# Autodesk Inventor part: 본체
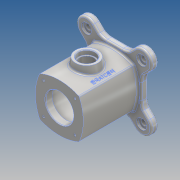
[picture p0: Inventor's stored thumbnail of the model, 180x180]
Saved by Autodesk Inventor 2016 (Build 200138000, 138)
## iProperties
Created: 2016-05
Part Number: 본체
Material: 알루미늄 6061
Document SubType Name: Modeling
Designer: Administrator
Density: 2.7 g/cm^3
Appearance: 알루미늄 - 평지
Mass: 1094 g
Surface Area: 856.534 cm^2
Volume: 405.187 cm^3
Author: Administrator
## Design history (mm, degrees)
sketch "스케치1"
  geometry: L1 (0, 0)-(-70.711, 70.711); L2 (0, 0)-(-118.695, 0); L3 (-70.711, 0)-(0, 70.711); L4 (7.604, 35.355)-(-78.314, 35.355); L5 (-35.355, -7.645)-(-35.355, 78.314); A1 r 86 centre (7.686, 35.355) between (-70.711, 70.711) and (-70.711, 0); A2 r 86 centre (-35.355, -7.686) between (0, 70.711) and (-70.711, 70.711); A3 r 85.162 centre (-77.476, 35.355) between (0, 0) and (0, 70.711); A4 r 85.162 centre (-35.355, 77.476) between (-70.711, 0) and (0, 0); 2 further points
  constraints: 12 point on circle, 10 end point, 4 centre point, 3 midpoint, 2 horizontal, 2 point on line, 1 perpendicular, 1 vertical
  dimensions: "d0" = 100 distance of L1.start L1.end; "d2" = 45 deg angle of L2 L1; "d3" = 100 distance of L3.start L3.end; "d4" = 50 distance from line of L1.start L3; "d103" = 86 distance of A1.centre L4.end; "d104" = 86 distance of A2.centre L5.end
extrude "돌출1" new body sketch "스케치1" distance "d9" = 98; taper "d10" = 0 deg
sketch "스케치4"
  geometry: L1 (35.355, -35.355)-(-104.696, -35.355); L2 (35.355, -35.355)-(35.355, -161.613); L3 (35.355, -35.355)-(-81.211, -151.922); L4 (-13.645, -35.355)-(-13.645, -61.423); L5 (35.355, -84.355)-(21.194, -84.355); L6 (-13.645, -49.517)-(-13.645, -35.355); L7 (-13.645, -35.355)-(35.355, -35.355); L8 (35.355, -35.355)-(35.355, -84.355); L9 (22.627, -22.627)-(-6.158, -51.413); L10 (-17.335, -62.59)-(-26.87, -72.125); L11 (8.121, -88.046)-(-1.414, -97.581); A1 r 85.162 centre (77.476, -35.355) between (0, 0) and (0, -70.711) reference; A2 r 85.162 centre (35.355, -77.476) between (70.711, 0) and (0, 0) reference; A3 r 70 centre (35.355, -35.355) between (-14.142, -84.853) and (0.117, -95.839); A4 r 18 centre (-14.142, -84.853) between (-26.87, -72.125) and (-1.414, -97.581); A5 r 25 centre (21.194, -109.355) between (21.194, -84.355) and (8.121, -88.046); A6 r 25 centre (-38.645, -49.517) between (-17.335, -62.59) and (-13.645, -49.517); 2 further points
  constraints: 22 end point, 11 point on circle, 4 centre point, 4 symmetric about line, 3 point on line, 2 collinear, 2 horizontal, 2 parallel, 2 tangent, 2 vertical, 1 horizontal alignment, 1 vertical alignment, 1 other
  dimensions: "d38" = 140 diameter of A3; "d39" = 45 deg angle of L2 L3; "d40" = 36 diameter of A4; "d42" = 49 distance between parallel lines of L4 L2; "d43" = 49 distance between parallel lines of L1 L5; "d44" = 50 diameter of A5; "d106" = 18 distance between parallel lines of L10 L3
extrude "돌출2" join sketch "스케치4" distance "d45" = 12; taper "d46" = 0 deg
node "작업 평면1"
node "작업 평면2"
node "작업 평면3"
node "작업 평면5"
  node "작업 평면4"
sketch "스케치6"
  geometry: L1 (49.517, -98)-(-21.194, -98) reference; L2 (-21.194, -98)-(49.517, -98) reference; L3 (49.517, -98)-(49.517, 0) reference; L4 (-21.194, 0)-(49.517, 0) reference; L5 (-21.194, -98)-(-21.194, 0) reference; L6 (-21.194, -98)-(-21.194, 0) reference; L7 (-21.194, -49)-(49.517, -49); L8 (49.517, -98)-(49.517, 0) reference; C1 r 20 at (14.162, -49)
  constraints: 3 midpoint, 2 end point, 1 centre point
  dimensions: "d50" = 40 diameter of C1
extrude "돌출3" join sketch "스케치6" distance "d51" = 50; taper "d52" = 10 deg
sketch "스케치7"
  geometry: L1 (21.194, -98)-(-49.517, -98) reference; L2 (-14.162, -98)-(-14.162, 12); L3 (0, 12)-(-28.323, 12) reference; L4 (10.838, -98)-(10.838, -86); L5 (10.838, -86)-(20.838, -86); L6 (20.838, -86)-(20.838, 0); L7 (20.838, 0)-(10.838, 0); L8 (10.838, 0)-(10.838, 12); L9 (0, 12)-(13.073, 12) reference; L10 (10.838, -98)-(-14.162, -98); L11 (10.272, 12)-(-14.162, 12); 1 further point
  constraints: 16 end point, 4 perpendicular, 3 point on line, 2 collinear, 2 midpoint, 1 vertical
  dimensions: "d53" = 70 diameter of L6 L2; "d54" = 86 distance between parallel lines of L7 L5; "d55" = 12 distance between parallel lines of L1 L5; "d56" = 50 diameter of L4 L2; "d57" = 50 diameter of L8 L2
revolve "회전1" sketch "스케치7" stored, may be unused: angle "d58" = 90 deg
sketch "스케치8"
  geometry: C1 r 20 at (0, 0) reference; 2 further points
  constraints: 1 coincident
hole "구멍1" sketch "스케치8" at (0, 0) diameter "d59" = 25; stored, may be unused: countersink angle "d63" = 90 deg, drill point angle "d65" = 0 deg; dims "d60" = 6, "d61" = 30, "d62" = 8, "d64" = 8
sketch "스케치10"
  geometry: A1 r 18 centre (84.853, -14.142) between (72.125, -26.87) and (97.581, -1.414) reference; A2 r 18 centre (84.853, 84.853) between (97.581, 72.125) and (72.125, 97.581) reference; A3 r 18 centre (-14.142, 84.853) between (-1.414, 97.581) and (-26.87, 72.125) reference; A4 r 18 centre (-14.142, -14.142) between (-26.87, -1.414) and (-1.414, -26.87) reference; 12 further points
  constraints: 4 coincident
hole "구멍2" sketch "스케치10" at (84.853, 84.853), (84.853, -14.142), (-14.142, -14.142), (-14.142, 84.853) diameter "d66" = 10; stored, may be unused: countersink angle "d70" = 90 deg, drill point angle "d72" = 0 deg; dims "d67" = 6, "d68" = 18, "d69" = 4, "d71" = 8
sketch "스케치11"
  geometry: L1 (-48.438, 119.148)-(147.325, -76.614); L2 (-55.014, -55.014)-(151.177, 151.177); L3 (10.355, 35.355)-(60.355, 35.355); A1 r 25 centre (35.355, 35.355) between (10.355, 35.355) and (60.355, 35.355) reference; A2 r 40 centre (35.355, 35.355) between (7.071, 63.64) and (7.071, 7.071); 2 further points
  constraints: 6 end point, 6 point on circle, 6 point on line, 1 centre point, 1 coincident, 1 horizontal, 1 midpoint
  dimensions: "d73" = 80 diameter of A2; "d74" = 45 deg angle of L1 L3; "d75" = 45 deg angle of L2 L3
hole "구멍3" sketch "스케치11" at (7.071, 63.64), (7.071, 7.071), (63.64, 7.071), (63.64, 63.64) diameter "d76" = 3.242; stored, may be unused: countersink angle "d80" = 90 deg, drill point angle "d82" = 118 deg; dims "d77" = 7, "d78" = 18, "d79" = 4, "d81" = 10
sketch "스케치12"
  geometry: L1 (75.355, -35.355)-(0.355, -35.355); L2 (35.355, -35.355)-(69.118, -69.118); C1 r 25 at (35.355, -35.355) reference; A1 r 40 centre (35.355, -35.355) between (75.355, -35.355) and (63.64, -63.64); 1 further point
  constraints: 4 end point, 2 point on circle, 2 point on line, 1 centre point, 1 coincident, 1 horizontal, 1 horizontal alignment, 1 other
  dimensions: "d83" = 80 diameter of A1; "d84" = 45 deg angle of L1 L2
hole "구멍4" sketch "스케치12" at (63.64, -63.64) diameter "d85" = 3.242; stored, may be unused: countersink angle "d89" = 90 deg, drill point angle "d91" = 118 deg; dims "d86" = 7, "d87" = 18, "d88" = 4, "d90" = 10
node "작업 평면6"
sketch "스케치13"
  geometry: L1 (49.162, -86)-(-20.838, -86) reference; L2 (49.162, 0)-(-20.838, 0) reference; C1 r 20 at (14.162, -49) reference; 3 further points
  constraints: 1 horizontal alignment, 2 other
  dimensions: "d96" = 29 distance of C1.centre point (43.162, -49)
feature "엠보싱1" sketch "스케치13" dims "d0" = 100, "d2" = 45 deg, "d3" = 100, "d4" = 50, "d38" = 140, "d39" = 45 deg, "d40" = 36, "d42" = 49, "d43" = 49, "d44" = 50, "d97" = 0.5, "d98" = 0, "d103" = 86, "d104" = 86, "d106" = 18
fillet "모깎기1" dims "d99" = 3
chamfer "모따기1" distance "d100" = 1; stored, may be unused: second distance "d101" = 2, angle "d102" = 45 deg
node "솔리드1"
mirror "대칭1"
mirror "대칭2"
pattern_circular "원형 패턴1" dims angle "d93" = 360 deg
node "투영된 루프2"
node "투영된 루프3"
other parameters: "d23" = 49, "d41" = 49, "d47" = 0, "d48" = 0, "d49" = 55, "d105" = 18
